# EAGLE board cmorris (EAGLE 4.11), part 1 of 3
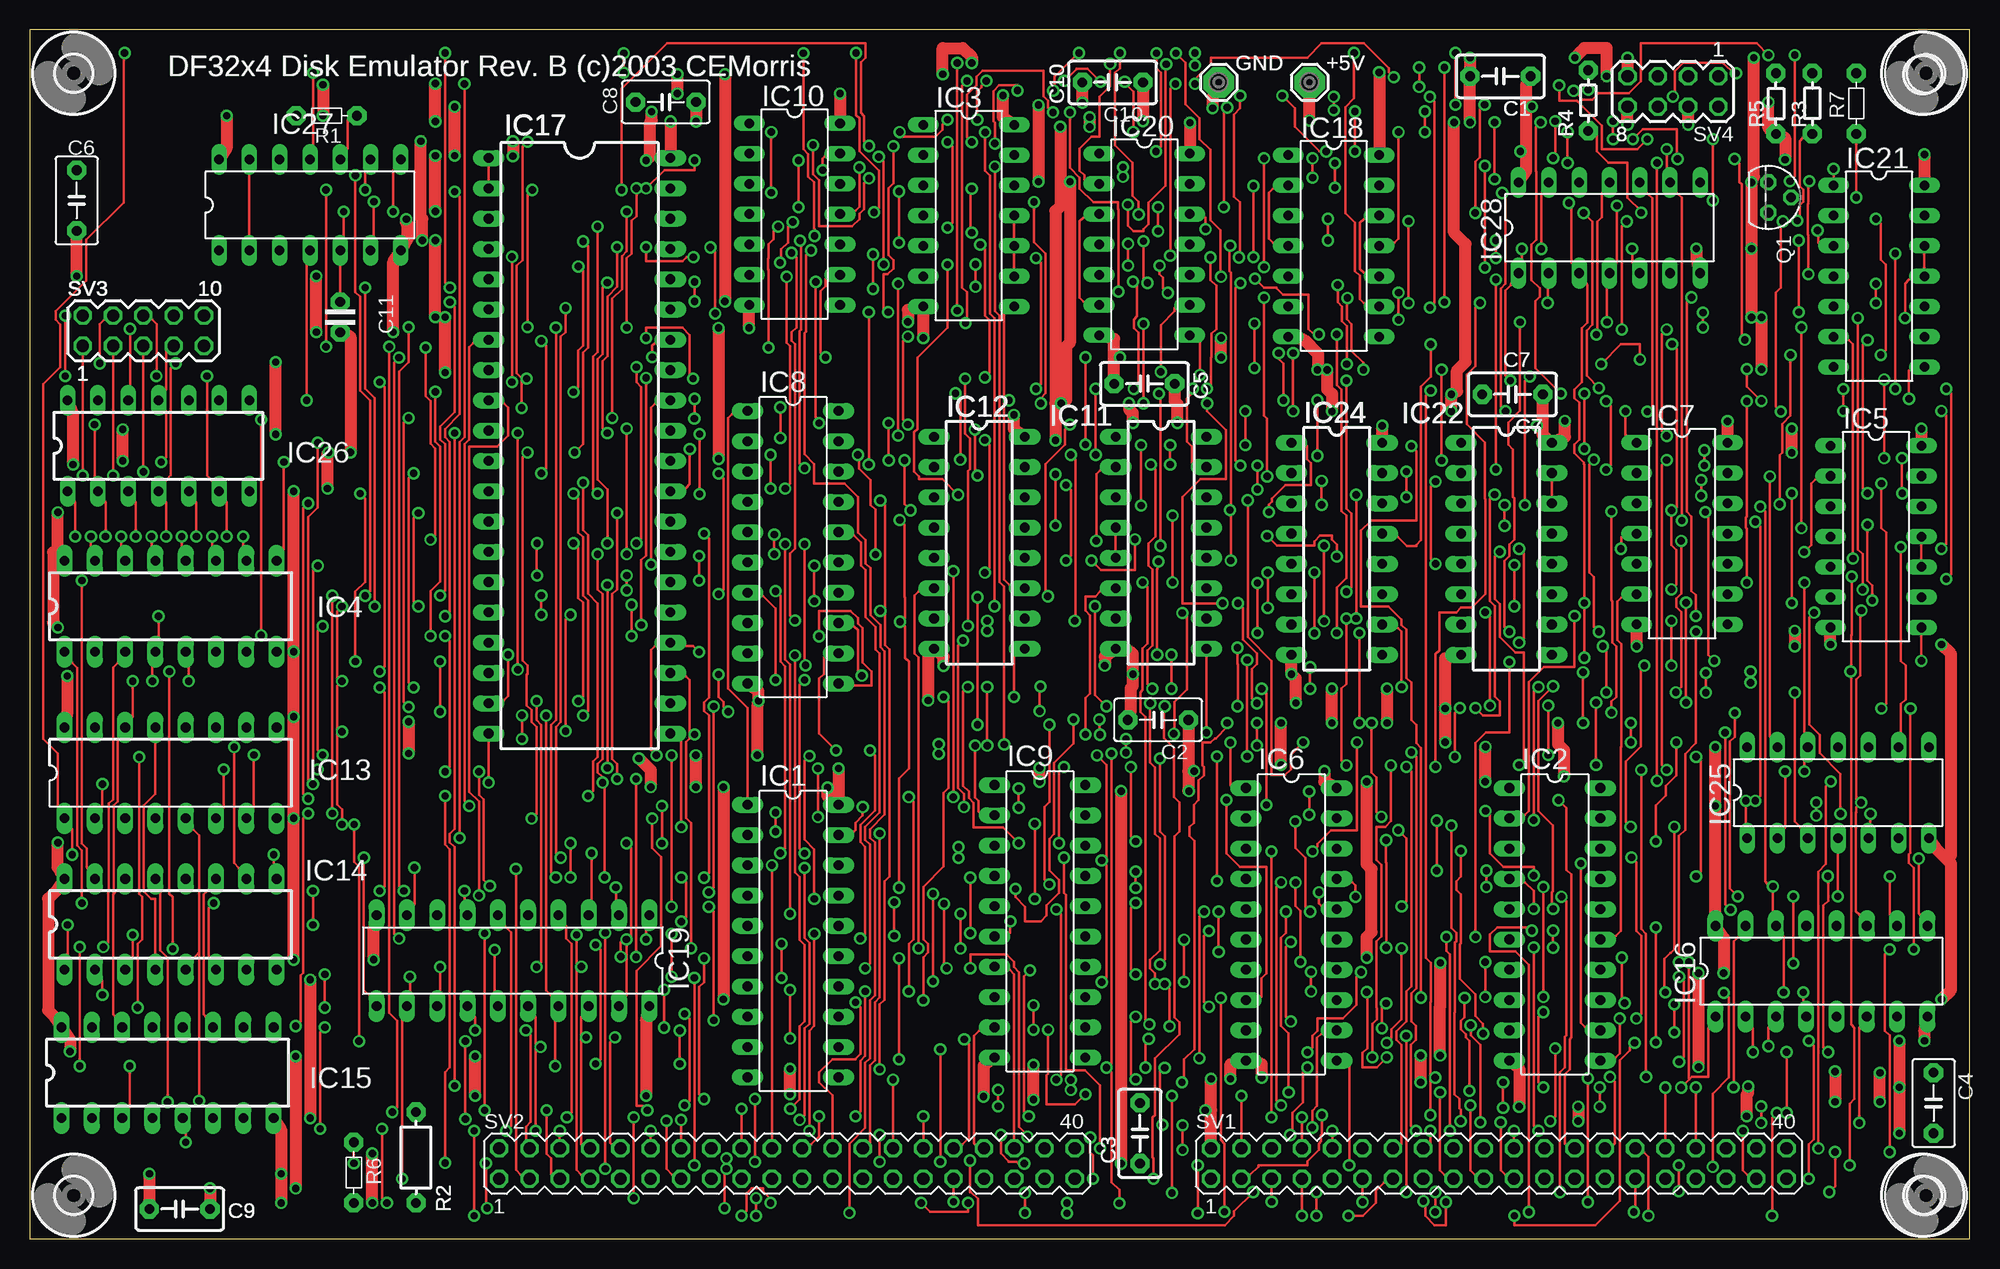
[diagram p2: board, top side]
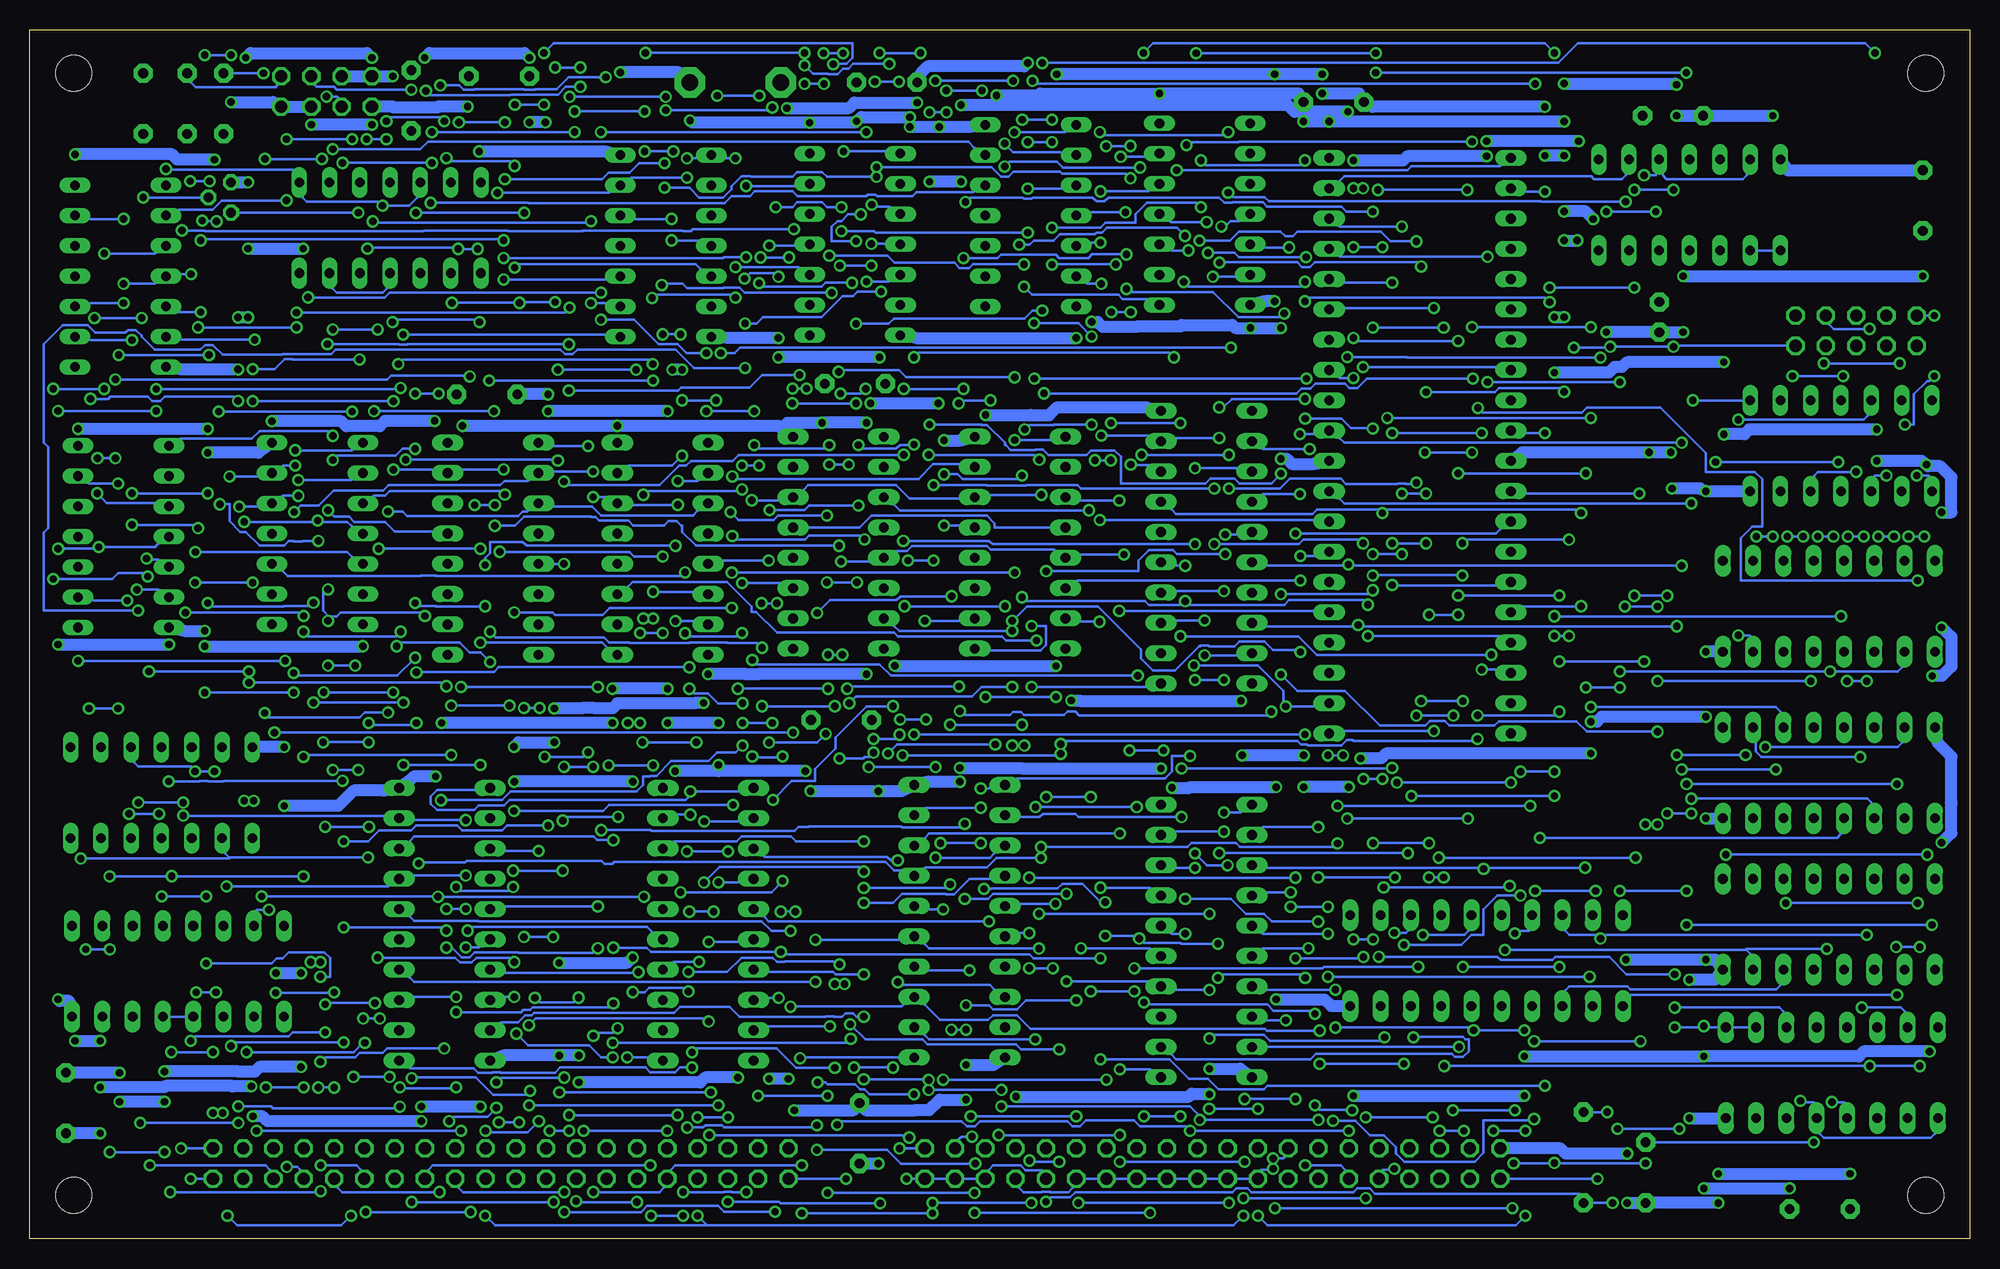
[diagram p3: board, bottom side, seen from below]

Size 162.67 x 101.4 mm. Coordinates in mm from the lower left corner, seen from the top.
Outline: 0,0 162.67,0 162.67,101.4 0,101.4 0,0
Copper layers (1*16): Top 0.035mm / dielectric 1.5mm / Bottom 0.035mm
Design rules "default": minimum track width 8mil, minimum drill 24mil, track to track 8mil, track to pad 8mil, pad to pad 8mil, via to via 8mil, smd to smd 8mil, copper to edge 40mil, drill to drill 8mil, minimum pad ring 10mil, minimum via ring 8mil, stop-mask expansion 4mil, vias tented up to drill 0mil, thermal gap 10mil
Net classes: 1 supply: width 1.016 mm

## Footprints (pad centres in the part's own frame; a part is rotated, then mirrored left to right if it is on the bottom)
SE14 = drill 1.397 pad 2.54 octagon: MP 0,0
C5B3.5 = drill 0.813 pad 1.6 octagon: 1 -2.54,0; 2 2.54,0
C-2,5 = drill 0.813 pad 1.6 octagon: 1 -1.27,0; 2 1.27,0
DIL20 = drill 0.813 long: 1 -11.43,-3.81; 2 -8.89,-3.81; 3 -6.35,-3.81; 4 -3.81,-3.81; 5 -1.27,-3.81; 6 1.27,-3.81; 7 3.81,-3.81; 8 6.35,-3.81; 9 8.89,-3.81; 10 11.43,-3.81; 11 11.43,3.81; 12 8.89,3.81; 13 6.35,3.81; 14 3.81,3.81; 15 1.27,3.81; 16 -1.27,3.81; 17 -3.81,3.81; 18 -6.35,3.81; 19 -8.89,3.81; 20 -11.43,3.81
DIL14 = drill 0.8 long: 1 -7.62,-3.81; 2 -5.08,-3.81; 3 -2.54,-3.81; 4 0,-3.81; 5 2.54,-3.81; 6 5.08,-3.81; 7 7.62,-3.81; 8 7.62,3.81; 9 5.08,3.81; 10 2.54,3.81; 11 0,3.81; 12 -2.54,3.81; 13 -5.08,3.81; 14 -7.62,3.81
DIL16 = drill 0.813 long: 1 -8.89,-3.81; 2 -6.35,-3.81; 3 -3.81,-3.81; 4 -1.27,-3.81; 5 1.27,-3.81; 6 3.81,-3.81; 7 6.35,-3.81; 8 8.89,-3.81; 9 8.89,3.81; 10 6.35,3.81; 11 3.81,3.81; 12 1.27,3.81; 13 -1.27,3.81; 14 -3.81,3.81; 15 -6.35,3.81; 16 -8.89,3.81
DIL40 = drill 0.813 long: 1 -24.13,-7.62; 2 -21.59,-7.62; 3 -19.05,-7.62; 4 -16.51,-7.62; 5 -13.97,-7.62; 6 -11.43,-7.62; 7 -8.89,-7.62; 8 -6.35,-7.62; 9 -3.81,-7.62; 10 -1.27,-7.62; 11 1.27,-7.62; 12 3.81,-7.62; 13 6.35,-7.62; 14 8.89,-7.62; 15 11.43,-7.62; 16 13.97,-7.62; 17 16.51,-7.62; 18 19.05,-7.62; 19 21.59,-7.62; 20 24.13,-7.62; 21 24.13,7.62; 22 21.59,7.62; 23 19.05,7.62; 24 16.51,7.62; 25 13.97,7.62; 26 11.43,7.62; 27 8.89,7.62; 28 6.35,7.62; 29 3.81,7.62; 30 1.27,7.62; 31 -1.27,7.62; 32 -3.81,7.62; 33 -6.35,7.62; 34 -8.89,7.62; 35 -11.43,7.62; 36 -13.97,7.62; 37 -16.51,7.62; 38 -19.05,7.62; 39 -21.59,7.62; 40 -24.13,7.62
TO92 = drill 0.813 octagon: 1 1.27,0; 2 0,1.905; 3 -1.27,0
R-5 = drill 0.813 pad 1.6 octagon: 1 -2.54,0; 2 2.54,0
R-7,5 = drill 0.813 pad 1.6 octagon: 1 -3.81,0; 2 3.81,0
MA20-2 = drill 1.016 octagon: 1 -24.13,-1.27; 2 -24.13,1.27; 3 -21.59,-1.27; 4 -21.59,1.27; 5 -19.05,-1.27; 6 -19.05,1.27; 7 -16.51,-1.27; 8 -16.51,1.27; 9 -13.97,-1.27; 10 -13.97,1.27; 11 -11.43,-1.27; 12 -11.43,1.27; 13 -8.89,-1.27; 14 -8.89,1.27; 15 -6.35,-1.27; 16 -6.35,1.27; 17 -3.81,-1.27; 18 -3.81,1.27; 19 -1.27,-1.27; 20 -1.27,1.27; 21 1.27,-1.27; 22 1.27,1.27; 23 3.81,-1.27; 24 3.81,1.27; 25 6.35,-1.27; 26 6.35,1.27; 27 8.89,-1.27; 28 8.89,1.27; 29 11.43,-1.27; 30 11.43,1.27; 31 13.97,-1.27; 32 13.97,1.27; 33 16.51,-1.27; 34 16.51,1.27; 35 19.05,-1.27; 36 19.05,1.27; 37 21.59,-1.27; 38 21.59,1.27; 39 24.13,-1.27; 40 24.13,1.27
MA05-2 = drill 1.016 octagon: 1 -5.08,-1.27; 2 -5.08,1.27; 3 -2.54,-1.27; 4 -2.54,1.27; 5 0,-1.27; 6 0,1.27; 7 2.54,-1.27; 8 2.54,1.27; 9 5.08,-1.27; 10 5.08,1.27
MA04-2 = drill 1.016 octagon: 1 -3.81,-1.27; 2 -3.81,1.27; 3 -1.27,-1.27; 4 -1.27,1.27; 5 1.27,-1.27; 6 1.27,1.27; 7 3.81,-1.27; 8 3.81,1.27
3,0 = hole 3: 0,0

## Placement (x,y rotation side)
+5V  SE14  [SE14]  107.31,96.99 0 top
C1  [C5B3.5]  123.31,97.5 180 top
C2  [C5B3.5]  94.61,43.52 180 top
C3  [C5B3.5]  93.09,8.85 90 top
C4  [C5B3.5]  159.63,11.39 270 top
C5  [C5B3.5]  93.47,71.72 180 top
C6  [C5B3.5]  3.93,87.08 270 top
C7  [C5B3.5]  124.33,70.83 180 top
C8  [C5B3.5]  53.34,95.34 180 top
C9  [C5B3.5]  12.57,2.5 180 top
C10  [C5B3.5]  90.8,96.99 180 top
C11  [C-2,5]  26.03,77.31 270 top
GND  SE14  [SE14]  99.69,96.99 0 top
IC1  74LS240N  [DIL20]  64,24.98 270 top
IC2  74LS244N  [DIL20]  127.88,26.38 270 top
IC3  74LS00N  [DIL14]  78.73,85.81 270 top
IC4  74LS138N  [DIL16]  11.81,53.05 0 top
IC5  74LS32N  [DIL14]  154.81,58.89 270 top
IC6  74LS244N  [DIL20]  105.79,26.38 270 top
IC7  74LS74N  [DIL14]  138.55,59.14 270 top
IC8  74LS240N  [DIL20]  64,58 270 top
IC9  74LS240N  [DIL20]  84.7,26.63 270 top
IC10  74LS04N  [DIL14]  64.13,85.94 270 top
IC11  74LS191N  [DIL16]  94.86,58.38 270 top
IC12  74LS191N  [DIL16]  79.62,58.38 270 top
IC13  74LS191N  [DIL16]  11.81,39.08 0 top
IC14  74LS191N  [DIL16]  11.81,26.38 0 top
IC15  74LS191N  [DIL16]  11.55,13.93 0 top
IC16  74LS191N  [DIL16]  150.24,22.44 0 top
IC17  DS1258  [DIL40]  46.1,66.51 270 top
IC18  74LS74N  [DIL14]  109.34,83.27 270 top
IC19  74LS240N  [DIL20]  40.51,23.33 180 top
IC20  74LS02N  [DIL14]  93.47,83.4 270 top
IC21  74LS01N  [DIL14]  155.06,80.73 270 top
IC22  74LS155N  [DIL16]  123.82,57.87 270 top
IC24  74LS155N  [DIL16]  109.6,57.87 270 top
IC25  74LS74N  [DIL14]  151.63,37.43 0 top
IC26  74LS30N  [DIL14]  10.79,66.51 0 top
IC27  74LS86N  [DIL14]  23.49,86.7 0 top
IC28  74LS07N  [DIL14]  132.46,84.8 0 top
Q1  2N3904  [TO92]  145.79,87.34 270 top
R1  1K  [R-5]  24.89,94.2 180 top
R2  1K  [R-7,5]  32.38,6.82 90 top
R3  220  [R-5]  149.47,95.21 270 top
R4  220  [R-5]  130.68,95.47 270 top
R5  220  [R-5]  146.43,95.21 90 top
R6  0  [R-5]  27.17,5.55 270 top
R7  4.7K  [R-5]  153.16,95.21 90 top
SV1  BUS1  [MA20-2]  123.19,6.31 0 top
SV2  BUS2  [MA20-2]  63.49,6.31 0 top
SV3  WRLOCK  [MA05-2]  9.52,76.16 0 top
SV4  PANEL LEDS  [MA04-2]  137.79,96.23 180 top
U$1  [3,0]  3.68,97.75 0 top
U$2  [3,0]  3.68,3.65 0 top
U$3  [3,0]  159,3.65 0 top
U$4  [3,0]  159,97.75 0 top

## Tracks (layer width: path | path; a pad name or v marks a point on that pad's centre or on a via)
0V  (via drill 0.61)
  Top 0.203: v58.41,6.74 v58.41,5.88 58.26,5.37 v58.26,2.58 | 14.13,23.93 14.19,23.99 14.19,33.85 13.71,34.33 IC13.5 | 14.13,23.93 13.71,23.51 IC14.5 | v13.08,8.09 13.08,8.8 IC15.5 | v14.19,11.57 14.19,23.86 14.13,23.93 | v38.35,2.58 38.25,2.68 v38.25,6.34 | R6.1 v27.17,6.34 | IC11.5 IC11.4 | v140.15,63.64 v140.15,62.32 | v147.06,20.66 147.06,25.31 IC16.14 146.17,27.57 v146.17,29.55 145.69,29.78 145.51,29.96 145.51,61 v145.11,61.41 | v148.71,20.66 148.71,19.95 IC16.4 | v94.64,56.81 94.56,56.73 94.56,56.17 94.53,56.15 v94.53,48.98 | v95.73,46.14 v95.73,48.98 | v103.3,46.14 103.7,45.73 v103.7,36.39 | v122.07,35.88 122.45,35.5 122.45,32.32 123.57,31.2 126.11,31.2 v126.11,30.47 | v34.82,6.36 34.82,13.98 35.22,14.39 35.22,32.68 34.82,33.08 v34.82,37.15 | v46.81,37.15 47.21,37.55 47.21,40.02 47.62,40.42 47.62,53.3 46.81,54.12 46.81,59.02 46.4,59.42 v46.4,63.41 | v62.12,65.75 v62.12,62.93 | v69.44,65.75 69.54,65.65 69.54,64.58 70.48,63.64 70.48,63.28 70.51,63.26 70.51,61.56 70.91,61.15 v70.91,57.39
  Bottom 0.203: SV2.33 79.7,4.28 79.34,3.92 77.82,3.92 77.8,3.95 77.14,3.95 77.11,3.92 75.59,3.92 75.23,4.28 SV2.29 SV2.27 SV2.25 SV2.23 SV2.21 SV2.19 SV2.17 59.38,5.8 58.49,5.8 v58.41,5.88 | v58.41,6.74 57.53,6.74 57.45,6.82 SV2.16 | IC15.1 2.92,8.8 3.25,8.47 12.24,8.47 12.57,8.8 IC15.5 13.08,11.44 14.07,11.44 v14.19,11.57 | v13.08,8.09 R6.1 | v38.35,2.58 v58.26,2.58 | v27.17,6.34 34.82,6.34 | 34.82,6.34 v38.25,6.34 | v140.15,62.32 141.42,62.32 IC7.12 143.66,61.41 v145.11,61.41 | v140.15,63.64 135.73,63.64 IC7.2 | IC16.5 IC16.4 | v148.71,20.66 v147.06,20.66 | v146.17,29.55 132.63,29.55 IC2.17 130.4,30.47 v126.11,30.47 | v94.64,56.81 92.32,56.81 IC11.5 90.06,57.7 89.1,57.7 88.69,58.1 82.39,58.1 82.11,57.82 76.78,57.82 76.73,57.77 IC12.5 74.52,57.39 v70.91,57.39 | v95.73,48.98 v94.53,48.98 | v95.73,46.14 95.75,46.17 103.27,46.17 v103.3,46.14 | v103.7,36.39 114.09,36.39 114.6,35.88 v122.07,35.88 | v46.81,37.15 v34.82,37.15 | v46.4,63.41 46.5,63.31 47.26,63.31 47.29,63.34 47.95,63.34 47.98,63.31 52.29,63.31 52.72,63.74 57.02,63.74 57.83,62.93 v62.12,62.93 | v69.44,65.75 v62.12,65.75 | v34.82,6.36 34.82,6.34
660-663\  (via drill 0.61)
  Top 0.203: v115.44,62.22 v115.44,64.35 | v141.24,48.48 140.74,48.98 140.74,60.72 v140.51,60.95 | v158.62,48.48 IC5.8 | v108.33,61.56 v108.33,63.56
  Bottom 0.203: v115.44,64.35 118.72,64.35 IC22.2 120.92,63.56 122.86,63.56 123.21,63.21 132.58,63.21 133.04,62.75 137.18,62.75 138.45,61.48 139.97,61.48 v140.51,60.95 | v115.44,62.22 114.45,62.22 IC24.14 112.11,61.56 v108.33,61.56 | v141.24,48.48 v158.62,48.48 | v108.33,63.56 106.7,63.56 IC24.2
(NED+EWL)\  (via drill 0.61)
  Top 0.203: v94.43,91.2 94.84,91.61 94.84,97.8 94.48,98.16 v94.48,99.43 | v96.11,99.43 96.9,98.64 96.9,95.16 98.09,93.97 98.09,92.24 99,91.33 99,85.43 99.84,84.59 99.84,80.73 v99.89,80.68 | v102.74,80.53 103.5,79.77 104.52,79.77 104.52,79.74 105.08,79.19 107.23,79.19 107.23,76.31 107.69,75.86 v108.1,75.86 | v109.6,75.86 109.6,71.62 110,71.21 110,61.05 110.41,60.64 110.41,55.44 109.6,54.62 v109.6,50.81 | v111.5,43.27 v111.5,50.81 | v112.52,43.27 112.52,39.1 112.92,38.7 112.92,35.8 v113.33,35.4 | v117.98,30.87 v117.98,35.07 | v122.14,29.5 v122.14,30.87 | v126.92,20.28 v126.92,29.5
  Bottom 0.203: v94.43,91.2 90.95,91.2 IC20.1 | v96.11,99.43 v94.48,99.43 | v99.89,80.68 100.2,80.99 102.28,80.99 v102.74,80.53 | v109.6,75.86 v108.1,75.86 | v111.5,50.81 v109.6,50.81 | v112.52,43.27 v111.5,43.27 | v113.33,35.4 117.65,35.4 v117.98,35.07 | v122.14,30.87 v117.98,30.87 | v122.14,29.5 122.47,29.17 126.59,29.17 v126.92,29.5 | v126.92,20.28 130.4,20.28 IC2.13
ACBUS\0  (via drill 0.61)
  Top 0.203: v67.61,40.96 66.19,42.38 66.19,46.98 66.59,47.38 66.59,48.76 IC8.12 | v70.45,40.96 70.86,40.55 70.86,35.93 69.64,34.71 69.64,33.29 70.05,32.88 70.05,25.59 v69.64,25.18 | v63.04,21.88 v63.04,24.75 | v55.72,6.16 v55.72,21.88 | v120.01,32.53 120.01,30.39 119.6,29.98 119.6,29.27 120.01,28.87 120.01,24.78 119.91,24.68 119.91,21.81 121.23,20.48 121.23,18.68 121.86,18.05 v121.86,17.21 | v113.79,15.23 112.95,14.39 111.76,14.39 111.76,15.58 112.16,15.99 112.16,20.64 v112.11,20.69 | v107.44,22.39 v107.44,20.74 | v94.76,23.02 95.17,23.43 95.17,33.74 94.76,34.15 v94.76,40.3 | v91.92,41.92 v91.92,40.78 | v89.73,42.28 89.68,42.33 v89.68,43.55 | v87.52,43.55 87.52,41.54 85.9,39.92 85.9,33.95 85.49,33.54 85.49,30.9 86.3,30.09 86.3,29.02 85.26,27.98 85.26,27.11 84.78,26.63 83.46,26.63 83.46,27.85 82.65,28.66 v82.65,29.35 | v72.49,25.41 v72.49,28.23
  Bottom 0.203: v70.45,40.96 v67.61,40.96 | v63.04,24.75 66.11,24.75 66.16,24.8 69.26,24.8 v69.64,25.18 70.12,25.41 v72.49,25.41 | v63.04,21.88 62.73,22.19 56.03,22.19 v55.72,21.88 | v55.72,6.16 52.72,6.16 52.37,5.8 SV2.11 | v120.01,32.53 122.78,32.53 IC2.3 | v121.86,17.21 120.87,16.22 115.77,16.22 114.78,15.23 v113.79,15.23 | v112.11,20.69 111.09,20.69 110.74,21.04 107.74,21.04 v107.44,20.74 | v107.44,22.39 104.19,22.39 102.99,23.58 100.38,23.58 100.02,23.23 99.36,23.23 99.33,23.25 94.99,23.25 v94.76,23.02 | v94.76,40.3 92.76,40.3 92.65,40.4 92.27,40.4 91.92,40.75 v91.92,40.78 | v91.92,41.92 90.09,41.92 v89.73,42.28 | v87.52,43.55 v89.68,43.55 | v82.65,29.35 82.06,29.35 82.04,29.38 76.5,29.38 76.09,29.78 74.39,29.78 72.84,28.23 v72.49,28.23
ACBUS\1  (via drill 0.61)
  Top 0.203: v48.25,5.88 v48.25,25.67 | v62.53,54.32 62.94,53.91 62.94,48.4 63.34,47.99 63.34,32.75 v62.94,32.35 | v47.11,32.35 47.11,28.46 IC19.3
  Bottom 0.203: v48.25,25.67 47.26,25.67 47.11,25.82 IC19.3 | v48.25,5.88 48.33,5.8 49.22,5.8 SV2.9 | v62.53,54.32 66.52,54.32 IC8.14 | v47.11,32.35 v62.94,32.35
ACBUS\2  (via drill 0.61)
  Top 0.203: 45.84,22.82 45.84,5.78 46.25,5.37 SV2.7 | 45.84,22.82 v45.84,25.49 | v70.05,22.7 70.45,23.1 70.45,33.06 70.05,33.47 70.05,34.53 71.27,35.75 71.27,49.09 70.91,49.44 70.91,51.32 70.1,52.13 70.1,56.07 69.69,56.48 69.69,58.41 69.11,58.99 IC8.16 | 45.84,22.82 v46.25,22.82
  Bottom 0.203: v45.84,25.49 42.36,25.49 42.03,25.82 IC19.5 | v70.05,22.7 54.27,22.7 54.15,22.82 v46.25,22.82
ACBUS\3  (via drill 0.61)
  Top 0.203: v36.44,29.17 36.44,28.46 IC19.7 | v31.36,29.17 30.96,29.58 30.96,72.73 31.77,73.55 v31.77,76.47 | v41.73,76.47 41.73,87.57 v42.13,87.97 | v49.63,87.97 49.63,96.46 53.44,100.27 70.1,100.27 70.1,99.07 69.69,98.67 69.69,94.42 69.97,94.15 69.97,92.06 v70.38,91.66 | v72.41,91.63 72.41,88.53 72,88.12 72,82.49 72.41,82.08 72.41,81.37 71.93,80.89 71.57,80.89 71.57,77.86 71.73,77.71 v71.98,77.71 | v70.35,64.94 v70.35,77.71 | v43.33,10.78 43.33,7.15 43.71,6.77 43.71,6.54 43.73,6.51 43.73,5.4 SV2.5 | v38.15,25.62 v38.15,10.78
  Bottom 0.203: v31.36,29.17 v36.44,29.17 | v41.73,76.47 v31.77,76.47 | v49.63,87.97 v42.13,87.97 | v70.38,91.66 70.4,91.63 v72.41,91.63 | v70.35,77.71 v71.98,77.71 | v70.35,64.94 70.33,64.91 68.83,64.91 IC8.18 | v38.15,10.78 v43.33,10.78 | v38.15,25.62 37.94,25.82 36.95,25.82 IC19.7
ACBUS\4  (via drill 0.61)
  Top 0.203: v32.25,31.13 32.25,28.08 IC19.9 | v40.76,31.03 40.76,5.78 41.17,5.37 SV2.3
  Bottom 0.203: 40.76,31.13 58.9,31.13 IC1.3 | 40.76,31.13 v32.25,31.13 | v40.76,31.03 40.76,31.13
ACBUS\5  (via drill 0.61)
  Top 0.203: v31.21,5.04 31.21,18.35 IC19.12 31.87,20.84 v31.87,21.98 | v53.82,21.98 v53.82,25.59
  Bottom 0.203: SV2.1 v31.21,5.04 | v53.82,25.59 59.28,25.59 IC1.5 | v31.87,21.98 v53.82,21.98
ACBUS\6  (via drill 0.61)
  Top 0.203: v37.33,17.49 37.33,18.58 IC19.14 | v41.6,17.49 42.01,17.08 42.01,9.82 41.6,9.41 41.6,8.34 SV2.4 | v53.18,17.72 v53.18,20.89
  Bottom 0.203: v37.33,17.49 v41.6,17.49 42.08,17.72 v53.18,17.72 | v53.18,20.89 58.9,20.89 IC1.7
ACBUS\7  (via drill 0.61)
  Top 0.203: v42.41,9.05 42.41,16.09 | 42.41,16.09 42.41,18.58 IC19.16 | v44.45,9.05 SV2.6 | 42.41,16.09 v42.82,16.09
  Bottom 0.203: v44.45,9.05 v42.41,9.05 | v42.82,16.09 IC1.9
ACBUS\8  (via drill 0.61)
  Top 0.203: 46.25,16.9 46.25,18.55 IC19.18 | 46.25,16.9 46.25,7.91 SV2.8 | 46.25,16.9 v46.65,16.9
  Bottom 0.203: v46.65,16.9 46.63,16.93 42.49,16.93 42.29,16.73 42.01,16.73 42.01,15.73 42.49,15.25 43.15,15.25 43.4,15.51 54.83,15.51 55.27,15.07 66.54,15.07 66.9,15.43 IC1.12
ACBUS\9  (via drill 0.61)
  Top 0.203: v49.07,16.9 48.66,16.5 48.66,8.04 48.79,7.91 SV2.10 | v63.75,20.87 v63.75,16.8 | v115.03,27.88 115.44,28.28 115.44,33.59 v114.75,34.28 | v84.27,28.51 v84.27,34.81 | v75.74,21.6 v75.74,28.94
  Bottom 0.203: v49.07,16.9 49.35,16.62 58.69,16.62 59.18,17.11 63.44,17.11 v63.75,16.8 | v63.75,20.87 66.54,20.87 IC1.14 68.96,21.6 v75.74,21.6 | v115.03,27.88 122.78,27.88 IC2.5 | v114.75,34.28 110.61,34.28 110.54,34.2 98.55,34.2 98.19,34.56 97.35,34.56 97.33,34.58 89.61,34.58 89.53,34.51 84.58,34.51 v84.27,34.81 | v84.27,28.51 82.32,28.51 81.89,28.94 v75.74,28.94
ACBUS\10  (via drill 0.61)
  Top 0.203: v65.78,25.59 65.78,17.87 65.38,17.46 v65.38,9.05 | v52.06,9.05 SV2.12 | v111.63,22.36 111.22,21.96 111.22,19.62 110.1,18.5 107.97,18.5 107.97,17.46 107.54,17.03 107.54,16.04 v107.13,15.63 | v95.17,14.34 94.76,14.34 94.76,9.77 v94.97,9.56
  Bottom 0.203: v65.78,25.59 66.9,25.59 IC1.16 | v52.06,9.05 v65.38,9.05 65.7,9.44 69.57,9.44 70.07,9.94 74.09,9.94 74.59,9.44 75.26,9.44 75.66,9.84 83,9.84 83.41,9.44 84.09,9.44 84.53,9.87 94.66,9.87 v94.97,9.56 | v111.63,22.36 111.68,22.31 122.78,22.31 IC2.7 | v107.13,15.63 106.8,15.96 100.05,15.96 98.42,14.34 v95.17,14.34
ACBUS\11  (via drill 0.61)
  Top 0.203: v64.56,9.97 64.97,10.38 64.97,17.64 65.38,18.05 65.38,24.83 64.97,25.23 v64.97,31.1 | v54.6,9.97 SV2.14 | v92.73,18.63 92.32,18.23 92.32,13.78 v92.73,13.37 | v87.3,12.48 v87.3,13.32 | v81.2,11.11 v81.2,12.48
  Bottom 0.203: v54.6,9.97 v64.56,9.97 64.77,10.48 65.4,11.11 v81.2,11.11 | v64.97,31.1 66.52,31.1 IC1.18 | v92.73,18.63 93.34,18.63 93.62,18.91 94.28,18.91 94.56,18.63 95.22,18.63 95.25,18.66 95.91,18.66 95.96,18.61 103.14,18.61 103.98,19.44 108.15,19.44 108.66,18.94 120.39,18.94 120.57,18.76 121.15,18.76 121.74,18.17 123.13,18.17 123.16,18.15 IC2.9 | v92.73,13.37 87.35,13.37 v87.3,13.32 | v81.2,12.48 v87.3,12.48
ACCLEAR\  (via drill 0.61)
  Top 0.203: v133.09,86.65 133.09,81.93 IC28.4 132.25,79.69 v132.25,76.87 | v151.25,89.73 IC21.1 | v94.23,5.04 94.23,6.74 94.15,6.82 94.15,10.17 94.36,10.38 94.36,15.13 96.39,17.16 96.39,18.17 95.98,18.58 95.98,33.74 96.39,34.15 96.39,36.61 95.93,37.07 95.93,41.19 95.12,42 95.12,44.62 v95.17,44.67 | v101.27,44.67 101.29,44.69 101.29,48.17 101.27,48.2 v101.27,49.57 | v124.07,50.91 123.67,51.32 123.67,56.86 124.07,57.26 124.07,58.23 124.48,58.64 124.48,62.12 124.38,62.22 124.38,66.2 123.97,66.61 123.97,68.47 124.96,69.46 v124.96,76.87
  Bottom 0.203: IC28.4 132.74,79.69 133.07,79.36 136.93,79.36 137.26,79.69 IC28.6 | IC28.12 130.19,87.31 130.86,86.65 v133.09,86.65 133.47,86.98 139.47,86.98 139.8,87.31 IC28.8 140.58,89.67 151.2,89.67 v151.25,89.73 | v101.27,44.67 v95.17,44.67 | v101.27,49.57 101.67,49.98 104.16,49.98 104.19,50 107.34,50 107.36,49.98 112.39,49.98 112.42,50 114.09,50 114.52,50.43 123.59,50.43 v124.07,50.91 | v124.96,76.87 125.17,77.08 132.05,77.08 v132.25,76.87 | v94.23,5.04 SV1.1
BAC1  (via drill 0.61)
  Top 0.203: v9.04,19.39 9.04,24.73 9.44,25.13 9.44,28.66 9.16,28.94 v9.16,40.4
  Bottom 0.203: v9.04,19.39 5.79,19.39 5.46,19.06 IC15.15 | v9.16,40.4 17.47,40.4 17.95,40.88 17.95,41.57 IC13.10
BAC2  (via drill 0.61)
  Top 0.203: v3.55,32.22 3.55,34.33 IC13.1 2.36,36.28 2.36,40.7 1.14,41.92 1.14,71.69 2.56,73.11 2.56,76.67 2.15,77.08 2.15,77.79 4.75,80.38 4.75,83.78 7.87,86.91 7.87,99.38 v7.95,99.45 | v20.44,32.22 20.44,31.51 IC14.9 | v119.98,9.87 120.01,9.89 120.01,10.81 119.88,10.94 119.88,11.72 119.48,12.13 119.48,18.96 119.5,18.99 119.5,24.85 119.6,24.96 119.6,25.67 119.2,26.07 v119.2,34.66 | v136.34,33.34 136.34,36.36 137.18,37.2 137.18,37.99 138.07,38.88 v138.07,41.64 | v134.26,43.27 v134.26,41.64 | v130.25,47.51 v130.25,43.27 | v107.36,46.14 v107.36,47.94 | v102.89,44.92 102.48,45.33 102.48,47.79 102.89,48.2 102.89,49.11 101.72,50.28 101.72,52.9 v101.32,53.3 | v100.02,53.3 96.64,53.3 96.64,62.19 98.17,63.72 100.3,63.72 100.3,67.83 98.73,69.41 v98.73,70.07 | v93.39,76.75 v93.39,70.07 | v77.77,98.62 v77.77,77.84 | v124.45,9.05 SV1.22
  Bottom 0.203: v20.44,32.22 v3.55,32.22 | v124.45,9.05 124.33,8.93 120.92,8.93 v119.98,9.87 | v119.2,34.66 122.65,34.66 123.06,34.25 126.41,34.25 126.82,34.66 130.27,34.66 130.68,34.25 133.37,34.25 134.28,33.34 v136.34,33.34 | v138.07,41.64 138.04,41.67 134.28,41.67 v134.26,41.64 | v134.26,43.27 134.08,43.09 130.42,43.09 v130.25,43.27 | v130.25,47.51 130.22,47.54 123.74,47.54 123.34,47.94 v107.36,47.94 | v107.36,46.14 106.98,45.76 105.81,45.76 104.97,44.92 v102.89,44.92 | v100.02,53.3 v101.32,53.3 | v93.39,70.07 v98.73,70.07 | v93.39,76.75 90.65,76.75 90.22,77.18 79.24,77.18 78.58,77.84 v77.77,77.84 | v77.77,98.62 34.49,98.62 32.84,100.27 8.76,100.27 v7.95,99.45
BAC3  (via drill 0.61)
  Top 0.203: v17.14,41.24 17.14,31.51 17.52,31.13 IC14.10
  Bottom 0.203: v17.14,41.24 6.04,41.24 5.71,41.57 IC13.15
BAC4  (via drill 0.61)
  Top 0.203: v78.66,51.4 78.66,64.38 78.84,64.55 78.84,67.12 78.43,67.53 v78.43,72.15 | v55.62,72.15 55.34,72.43 55.34,73.52 55.32,73.55 55.32,74.97 55.34,74.99 55.34,75.81 54.73,76.42 51.68,76.42 v51.68,75.55 | v42.9,75.3 43.3,74.89 43.3,64.61 v42.9,64.2 | v32.18,64.2 31.77,63.79 31.77,46.65 v32.18,46.24 | v29.33,46.24 29.74,45.83 29.74,29.58 v29.33,29.17 | v23.74,26.33 v23.74,29.17 | v3.17,26.33 3.17,23.89 IC14.1 | v128.19,36.79 128.85,36.13 128.85,30.95 129.26,30.54 129.26,16.88 129.13,16.75 129.13,14.21 128.72,13.8 128.72,7.99 128.8,7.91 SV1.26 | v102.89,43.27 v102.89,41.36 | v100.4,43.27 100.4,42.91 99.46,41.97 99.36,41.97 99,41.62 98.32,41.62 98.32,39.71 98.45,39.59 98.45,38.88 98.01,38.44 98.01,36.79 97.61,36.39 97.61,34.89 97.25,34.53 97.25,33.8 97.66,33.39 97.66,15.91 96.79,15.05 96.79,13.27 96.64,13.12 v96.62,13.12 | v88.51,12.13 87.65,11.27 85.26,11.27 85.26,13.7 85.39,13.83 v85.39,17.54 | v84.17,19.6 v84.17,17.54 | v74.93,20 74.93,23.61 75.33,24.02 75.33,24.73 74.93,25.13 74.93,29.53 76.63,31.23 76.63,37.4 77.03,37.81 77.03,45.05 v76.63,45.45 | v82.52,45.45 82.52,48.83 IC12.9
  Bottom 0.203: v78.66,51.4 77.44,51.4 77.44,49.82 77.92,49.34 82.14,49.34 IC12.9 | v55.62,72.15 v78.43,72.15 | v51.68,75.55 51.43,75.3 v42.9,75.3 | v32.18,64.2 v42.9,64.2 | v29.33,46.24 v32.18,46.24 | v23.74,29.17 v29.33,29.17 | v3.17,26.33 v23.74,26.33 | v128.19,36.79 123.06,36.79 122.35,37.5 111.78,37.5 111.22,38.06 111.22,38.77 110.66,38.77 110.61,38.82 110.13,38.82 108.89,40.07 105.76,40.07 105.05,40.78 103.48,40.78 v102.89,41.36 | v100.4,43.27 v102.89,43.27 | v96.62,13.12 95.93,13.12 95.75,12.94 93.47,12.94 93.06,12.54 92.65,12.54 92.25,12.13 v88.51,12.13 | v84.17,17.54 v85.39,17.54 | v84.17,19.6 82.24,19.6 81.91,19.27 79.88,19.27 79.14,20 v74.93,20 | v82.52,45.45 v76.63,45.45
BAC5  (via drill 0.61)
  Top 0.203: v132.51,13.58 132.91,13.17 132.91,8.01 132.81,7.91 SV1.28 | v135.53,13.58 135.53,25.59 135.12,26 v135.12,39.33 | v137.26,39.33 136.85,39.74 136.85,64.91 v137.26,65.32 | v130.35,70.88 v130.35,66.26 | v128.39,70.88 126.26,73.01 126.26,78.65 126.61,79.01 126.61,79.72 125.93,80.4 125.93,83.38 126.34,83.78 126.34,89.5 126.28,89.55 126.28,93.23 v126.69,93.64 | v122.83,88.86 v122.83,93.64 | v109.44,88.15 v109.44,90.21 | v91.66,89.88 v91.66,89.06 | v70.38,88.94 69.97,88.53 69.97,86.37 69.57,85.97 69.57,85.53 68.96,84.92 66.16,84.92 66.16,88.79 65.68,89.27 v65.68,91.73 | v41.73,92.01 41.32,91.61 41.32,82.08 40.84,81.6 40.84,72.61 41.24,72.2 | v41.24,69.69 41.24,72.2 | v4.36,55.21 4.36,33.16 4.77,32.75 4.77,31.18 4.82,31.13 IC14.15 | v87.62,51.83 87.7,51.91 87.7,65.34 v87.3,65.75 | v78.02,65.34 78.02,70.5 v77.62,70.9 | v41.65,72.15 41.32,72.15 41.24,72.2
  Bottom 0.203: v135.53,13.58 v132.51,13.58 | v137.26,39.33 v135.12,39.33 | v137.26,65.32 136.88,65.7 131.97,65.7 131.41,66.26 v130.35,66.26 | v128.39,70.88 v130.35,70.88 | v122.83,93.64 v126.69,93.64 | v122.83,88.86 114.68,88.86 114.14,89.4 112.39,89.4 111.58,90.21 v109.44,90.21 | v109.44,88.15 107.36,88.15 106.55,87.34 104.52,87.34 103.83,88.02 103.83,88.28 103.04,89.06 103.02,89.06 102.94,89.14 102.28,89.14 102.2,89.06 98.73,89.06 98.32,89.47 96.24,89.47 95.83,89.06 v91.66,89.06 | v91.66,89.88 82.04,89.88 81.25,89.09 80.59,89.09 80.18,89.5 76.27,89.5 76.12,89.34 70.79,89.34 v70.38,88.94 | v65.68,91.73 65.43,91.99 61.31,91.99 61.28,92.01 v41.73,92.01 | v41.24,69.69 40.86,69.3 32.51,69.3 32.1,69.71 25.93,69.71 22.12,65.9 22.12,64.3 18.84,64.3 18.82,64.33 18,64.33 17.39,63.72 17.39,59.73 18.23,59.73 19.17,58.79 19.17,55.21 v4.36,55.21 | v87.62,51.83 84.73,51.83 IC12.10 | v87.3,65.75 87.27,65.72 78.41,65.72 v78.02,65.34 | v77.62,70.9 56.46,70.9 56.05,71.31 55.29,71.31 54.86,71.74 52.39,71.74 52.01,71.36 51.35,71.36 50.57,72.15 v41.65,72.15
BAC6  (via drill 0.61)
  Top 0.203: v155.98,30.39 155.98,27.22 IC16.10 | v139.72,30.39 140.13,30.8 140.13,40.02 v139.72,40.42 | v127.33,44.72 v127.33,40.58 | v122.45,44.72 122.45,52.13 v122.04,52.54 | v103.81,55.87 v103.81,52.92 | v80.08,55.87 80.49,56.27 80.49,66.59 v80.08,66.99 | v135.73,1.94 135.73,6.87 135.35,7.25 SV1.30 | v146.1,1.94 146.1,10.15 v146.5,10.55 | v147.31,15.66 v147.31,10.55 | v150.8,15.66 150.39,16.07 150.39,27.95 150.8,28.36 150.8,30.39 v150.77,30.42
  Bottom 0.203: v139.72,30.39 150.77,30.39 | 150.77,30.39 v155.98,30.39 | v139.72,40.42 139.57,40.58 v127.33,40.58 | v122.45,44.72 v127.33,44.72 | v122.04,52.54 118.82,52.54 118.61,52.34 114.62,52.34 114.04,52.92 v103.81,52.92 | v80.08,55.87 v103.81,55.87 | v80.08,66.99 77.11,66.99 IC12.1 | v135.73,1.94 136.55,1.13 145.28,1.13 v146.1,1.94 | v147.31,10.55 v146.5,10.55 | v150.8,15.66 v147.31,15.66 | v150.77,30.42 150.77,30.39
BAC7  (via drill 0.61)
  Top 0.203: 139.17,13.39 139.37,13.58 140.74,13.58 140.74,17.67 IC16.1 | 139.17,13.39 v138.48,12.69 | v137.16,12.69 SV1.32 | v103.75,63.95 103.75,68.8 103.5,69.05 v103.5,78.93 | v110.48,78.91 110.43,78.85 110.43,77.13 110.84,76.72 110.84,74.46 111.83,73.47 v111.83,72.89 | v118.38,65.27 v118.38,72.89 | v131.16,65.34 130.75,64.94 130.75,55.89 131.16,55.49 131.16,51.32 v131.57,50.91 | v139.72,50.91 139.72,41.59 138.81,40.68 138.81,34.3 138.3,33.8 v138.3,23.2 | v139.11,23.2 139.11,13.45 139.17,13.39
  Bottom 0.203: v138.48,12.69 v137.16,12.69 | v103.75,63.95 103.53,63.72 88.16,63.72 86.91,64.96 84.73,64.96 IC12.15 | v103.5,78.93 103.75,79.19 110.21,79.19 v110.48,78.91 | v118.38,72.89 v111.83,72.89 | v118.38,65.27 118.46,65.34 v131.16,65.34 | v131.57,50.91 131.95,50.53 133.73,50.53 133.75,50.51 134.39,50.51 134.41,50.53 139.34,50.53 v139.72,50.91 | v139.11,23.2 v138.3,23.2
BAC8  (via drill 0.61)
  Top 0.203: v142.16,42.46 142.16,28.05 v142.62,27.6 | v98.67,42.46 IC11.9 | v142.87,12.71 142.87,24.93 143.25,25.31 IC16.15 | v139.69,12.71 SV1.34
  Bottom 0.203: v142.16,42.46 v98.67,42.46 | v142.62,27.6 142.64,27.57 143.63,27.57 IC16.15 | v142.87,12.71 v139.69,12.71
BAC11  (via drill 0.61)
  Top 0.203: v97.53,71.31 97.45,71.23 97.45,70.88 97.05,70.47 97.05,66.87 97.45,66.46 97.45,65.09 IC11.15 | v98.7,71.31 99.06,71.67 99.06,73.9 99.08,73.93 99.08,75.91 99.49,76.31 99.49,79.92 99,80.4 v99,82.31 | v101.39,82.31 101.47,82.39 101.47,86.93 100.98,87.41 100.98,94.3 101.49,94.81 v101.49,95.87 | v105.02,95.87 106.09,94.81 106.09,93.26 108.15,91.2 v108.71,91.2 | v111.12,94.55 v111.12,91.2 | v116.99,92.82 v116.99,94.55 | v128.95,90.23 v128.95,92.82 | v136.44,38.42 v136.44,90.23 | v151.02,38.37 150.62,37.96 150.62,31.43 149.96,30.77 149.96,27.98 149.98,27.95 v149.98,7.58
  Bottom 0.203: v98.7,71.31 v97.53,71.31 | v101.39,82.31 v99,82.31 | v105.02,95.87 v101.49,95.87 | v111.12,91.2 v108.71,91.2 | v116.99,94.55 v111.12,94.55 | v128.95,92.82 v116.99,92.82 | v136.44,90.23 v128.95,90.23 | v136.44,38.42 146.35,38.42 146.4,38.37 147.7,38.37 147.75,38.42 148.43,38.42 148.48,38.37 v151.02,38.37 | SV1.40 v149.98,7.58
BADDAC\  (via drill 0.61)
  Top 0.203: v116.23,9.05 115.82,9.46 115.82,16.27 116.23,16.68 116.23,17.84 115.84,18.23 115.84,20.59 116.25,20.99 116.25,40.4 v115.84,40.81 | v119.5,40.42 119.5,44.11 v119.91,44.51 | v121.23,44.51 121.86,43.88 123.26,43.88 123.26,45.07 122.86,45.48 122.86,53.07 122.45,53.48 122.45,62.04 v122.83,62.42 | v109.22,9.05 SV1.10
  Bottom 0.203: v116.23,9.05 v109.22,9.05 | v115.84,40.81 116.23,40.42 v119.5,40.42 | v121.23,44.51 v119.91,44.51 | v122.83,62.42 123.13,62.73 132.48,62.73 132.89,62.32 133.8,62.32 IC7.3
BBREAK\  (via drill 0.61)
  Top 0.203: v104.11,32.5 v104.11,10.2 | v107.56,32.5 107.97,32.91 107.97,33.13 109.09,34.25 111.3,34.25 v111.3,41.64 | v106.78,41.64 105.73,40.6 105.73,39.38 105.25,38.9 104.11,38.9 104.11,48.48 102.13,50.46 v102.13,61.94 | v106.68,10.2 SV1.8 | v66.49,89.62 66.49,90.59 66.65,90.74 IC10.13 | IC17.1 IC17.2 | v8.63,46.77 8.63,43.83 IC13.14 7.39,41.92 7.39,36.69 7.03,36.34 7.03,29.04 7.09,28.98 | v10.28,46.77 10.28,47.92 IC4.4 10.79,50.56 v10.79,52.21 | 7.09,28.98 6.98,28.87 6.98,18.81 7.11,18.68 IC15.14 | 7.09,28.98 7.36,29.25 IC14.14 | v35.63,87.82 36.04,87.41 36.04,69.15 34.82,67.93 34.82,67.22 35.22,66.81 35.22,52.62 v34.82,52.21 | v77.85,62.4 76.53,63.72 74.57,63.72 74.57,63.95 74.16,64.35 74.16,67.65 74.44,67.93 74.44,73.9 76.96,76.42 v76.96,81.7 | v71.6,81.73 71.6,90.34 v71.19,90.74
  Bottom 0.203: v104.11,10.2 v106.68,10.2 | v107.56,32.5 v104.11,32.5 | v106.78,41.64 v111.3,41.64 | v102.13,61.94 99.97,61.94 IC11.14 97.76,62.85 97.4,63.21 90.04,63.21 88.9,62.07 84.73,62.07 IC12.14 82.14,62.4 v77.85,62.4 | v66.49,89.62 47.16,89.62 46.81,89.98 39.39,89.98 IC17.1 | v10.28,46.77 v8.63,46.77 | v35.63,87.82 37.18,87.82 IC17.2 | v10.79,52.21 v34.82,52.21 | v76.96,81.7 76.93,81.73 v71.6,81.73 | v71.19,90.74 69.23,90.74 IC10.13
BIOP1  (via drill 0.61)
  Top 0.203: v116.86,3.16 117.01,3.01 117.01,1.92 117.8,1.13 118.74,1.13 v118.74,3.09 | v130.65,13.47 v130.65,3.09 | v120.72,12.41 120.72,16.6 120.42,16.9 120.42,17.16 120.01,17.56 120.01,18.27 120.31,18.58 v120.31,20.21 | v116.66,20.23 116.66,41.16 116.25,41.57 116.25,43.12 115.84,43.52 115.84,46.65 115.44,47.05 115.44,51.09 115.03,51.5 115.03,51.93 113.91,53.05 111.63,53.05 111.63,59.4 112.49,60.26 116.25,60.26 116.25,66.08 v115.84,66.48 | v111.76,3.09 SV1.11
  Bottom 0.203: v111.76,3.09 116.78,3.09 v116.86,3.16 | v130.65,3.09 v118.74,3.09 | v130.65,13.47 130.58,13.55 125.29,13.55 123.82,12.08 121.05,12.08 v120.72,12.41 | v120.31,20.21 119.93,19.82 117.06,19.82 v116.66,20.23 | v115.84,66.48 118.72,66.48 IC22.1
BIOP2  (via drill 0.61)
  Top 0.203: v110.56,1.94 111.78,1.94 112.87,3.04 112.87,4.03 113.56,4.71 SV1.13 | v107.89,3.92 v107.89,1.94 | v102.59,3.92 100.98,2.32 100.98,1.92 100.2,1.13 79.5,1.13 79.5,3.37 78.94,3.92 78.84,3.92 v78.84,6.57 | v76.35,15.89 v76.35,6.46 | v93.87,18 93.54,18.33 93.54,43.78 93.14,44.18 93.14,45.83 93.31,46.01 93.31,49.52 93.72,49.92 93.72,54.65 v93.31,55.06 | v95.83,60.67 v95.83,55.06 | v103.91,60.95 103.91,61.58 104.16,61.84 104.16,62.09 105.28,63.21 107.41,63.21 107.41,65.06 107.08,65.39 107.08,66.48 IC24.1
  Bottom 0.203: v107.89,1.94 v110.56,1.94 | v107.89,3.92 104.49,3.92 104.47,3.95 103.81,3.95 103.78,3.92 v102.59,3.92 | v78.84,6.57 78.73,6.46 v76.35,6.46 | v76.35,15.89 79.55,15.89 79.95,16.29 87.4,16.29 87.83,16.73 92.6,16.73 v93.87,18 | v95.83,55.06 v93.31,55.06 | v95.83,60.67 99.92,60.67 100.3,60.29 103.25,60.29 v103.91,60.95
BMB0  (via drill 0.61)
  Top 0.203: v118.26,12.28 118.26,5.75 118.64,5.37 SV1.17 | v105.56,12.28 105.56,17.23 104.92,17.87 104.92,25.26 105.33,25.67 v105.33,27.45 | v107.36,27.45 106.95,27.85 106.95,31.94 106.12,32.78 v106.12,35.01
  Bottom 0.203: v105.56,12.28 v118.26,12.28 | v107.36,27.45 v105.33,27.45 | v106.12,35.01 103.27,35.01 IC6.2
BMB1  (via drill 0.61)
  Top 0.203: v104.92,29.91 104.52,29.5 104.52,11.59 v104.92,11.19 | v120.8,11.19 120.8,5.75 121.18,5.37 SV1.19
  Bottom 0.203: v104.92,29.91 103.27,29.91 IC6.4 | v120.8,11.19 v104.92,11.19
BMB2  (via drill 0.61)
  Top 0.203: v123.34,9.77 123.34,5.75 123.72,5.37 SV1.21 | v121.64,9.77 121.64,16.27 120.82,17.08 v120.82,17.92 | v105.73,18.23 105.33,18.63 105.33,24.5 v105.73,24.91
  Bottom 0.203: v121.64,9.77 v123.34,9.77 | v120.82,17.92 120.24,18.5 106.02,18.5 v105.73,18.23 | v105.73,24.91 103.27,24.91 IC6.6
BMB3  (via drill 0.61)
  Top 0.203: v80.11,92.8 80.11,89.57 80.51,89.17 80.51,77.61 80.89,77.23 v80.89,53.05 | v89.33,53.05 89.33,45.63 v90.29,44.67 | v100.35,36.82 100.35,32.32 101.47,31.2 103.7,31.2 103.7,22.26 103.27,21.83 103.27,20.31 IC6.8 | v117.85,2.25 v117.85,3.92 | v100.17,2.27 100.17,7.99 99.87,8.29 v99.87,20.21
  Bottom 0.203: v80.11,92.8 80.08,92.82 75.89,92.82 IC3.1 | v89.33,53.05 v80.89,53.05 | v90.29,44.67 92.5,44.67 95.12,42.05 95.12,41.11 96.82,39.41 96.82,38.39 98.78,38.39 v100.35,36.82 | v117.85,3.92 126.34,3.92 126.69,4.28 SV1.23 | v117.85,2.25 111.43,2.25 110.89,2.78 104.97,2.78 104.47,2.27 v100.17,2.27 | v99.87,20.21 100.68,20.21 IC6.8
BMB4  (via drill 0.61)
  Top 0.203: v110.64,6.16 110.64,14.41 IC6.11 | v80.92,91.86 80.92,93.59 80.79,93.71 80.79,96.25 81.28,96.74 82.82,96.74 v82.82,96.3 | v85.82,96.3 85.92,96.41 85.92,97.47 87.9,99.45 v87.98,99.45 | v91.41,99.45 91.41,98.18 91,97.78 91,91.71 92.48,90.23 92.48,87.49 92.98,86.98 v92.98,85.92 | v93.39,83.68 93.39,80.51 v93.72,80.17 | v101.52,80.15 101.11,79.74 101.11,65.27 v101.52,64.86 | v102.94,62.85 v102.94,64.86 | v111.22,52.03 v111.22,62.4 | v110.41,52.03 110.41,46.55 110,46.14 110,40.12 v110.41,39.71 | v114.14,39.71 114.14,35.04 113.66,34.56 112.92,34.56 112.92,31.76 113.33,31.36 113.33,25.36 112.92,24.96 112.92,19.39 112.97,19.34 112.97,18.43 112.57,18.02 v112.57,15.23
  Bottom 0.203: v110.64,6.16 128.88,6.16 129.23,5.8 SV1.25 | v80.92,91.86 80.21,91.15 76.22,91.15 IC3.2 | v85.82,96.3 v82.82,96.3 | v91.41,99.45 v87.98,99.45 | v92.98,85.92 94.05,85.92 94.61,85.36 94.94,85.36 95.42,84.87 95.42,83.68 v93.39,83.68 | v93.72,80.17 95.93,80.17 96.26,79.84 101.21,79.84 v101.52,80.15 | v102.94,64.86 v101.52,64.86 | v102.94,62.85 103.09,62.7 110.92,62.7 v111.22,62.4 | v110.41,52.03 v111.22,52.03 | v114.14,39.71 v110.41,39.71 | v112.57,15.23 110.89,15.23 IC6.11
BMB6  (via drill 0.61)
  Top 0.203: v134.51,2.25 134.62,2.35 SV1.29 | v125.7,2.25 125.7,22.97 124.58,24.09 122.45,24.09 122.45,25.51 123.06,26.12 125.95,26.12 v125.95,25.84 | v155.27,63.34 155.27,59.63 155.67,59.22 155.67,44.9 v155.27,44.49 | v157.7,44.49 157.7,32.37 157.58,32.25 157.58,31.53 157.98,31.13 v157.98,24.27 | v155.95,24.27 155.55,23.86 155.55,17.46 155.95,17.06 v155.95,7.28 | v151.38,7.28 151.38,4.41 v150.9,3.92 | v138.27,6.16 v138.27,4
  Bottom 0.203: v125.7,2.25 v134.51,2.25 | v125.95,25.84 125.65,26.15 110.89,26.15 110.51,25.77 IC6.15 | v155.27,63.34 157.68,63.34 IC5.13 | v157.7,44.49 v155.27,44.49 | v155.95,24.27 v157.98,24.27 | v151.38,7.28 v155.95,7.28 | v150.9,3.92 138.35,3.92 v138.27,4 | v138.27,6.16 135.28,6.16 134.92,5.8 SV1.29
BMB7  (via drill 0.61)
  Top 0.203: v111.17,28.69 111.17,29.63 110.89,29.91 IC6.17 | v128.44,28.69 128.85,28.28 128.85,17.06 128.72,16.93 128.72,14.39 128.32,13.98 v128.32,3.92 | v132.63,61 132.61,60.97 132.61,53.56 132.71,53.45 132.71,50.03 133.04,49.7 133.04,45.45 132.63,45.05 v132.63,44.13 | v142.97,44.11 142.97,42.1 142.56,41.69 142.56,29.38 v143.23,28.71
  Bottom 0.203: IC24.3 106.7,61.02 107.06,60.67 114.78,60.67 115.51,61.41 118.72,61.41 IC22.3 120.92,61.02 120.95,61 121.36,61 121.74,60.62 131.03,60.62 131.41,61 v132.63,61 | v111.17,28.69 v128.44,28.69 128.93,28.71 v143.23,28.71 | v128.32,3.92 136.5,3.92 136.85,4.28 SV1.31 | v132.63,44.13 134.59,44.13 135,43.73 142.59,43.73 v142.97,44.11
BMB8  (via drill 0.61)
  Top 0.203: v129.53,52.24 129.53,47.97 126.97,47.97 125.7,46.7 125.7,35.88 125.37,35.55 IC2.2 | v137.66,54.47 138.07,54.88 138.07,57.77 137.66,58.18 v137.66,61.1 138.12,61.35 138.12,74.64 v137.71,75.04 | v117.47,75.02 117.47,72.3 116.66,71.49 116.66,58.59 116.25,58.18 116.25,58.1 115.46,58.1 114.7,58.87 IC24.13 | v141.12,6.03 141.12,12.18 142.46,13.53 142.46,20.23 v142.06,20.64 | v137.16,20.66 137.08,20.74 137.08,23.48 137.56,23.96 137.59,23.96 137.89,24.27 v137.89,34.56 | v134.23,34.56 133.83,34.96 133.83,40.04 135.07,41.29 135.07,47.77 v135.38,48.07 | v137.66,51.83 v137.66,48.07
  Bottom 0.203: v129.53,52.24 129.81,52.52 136.62,52.52 136.93,52.21 137.59,52.21 | 137.59,52.21 138.07,52.69 138.07,54.47 v137.66,54.47 | v137.66,61.1 137.13,60.57 135.88,60.57 135.45,60.14 132.89,60.14 132.08,59.32 128.93,59.32 IC22.13 | v117.47,75.02 117.5,75.04 130.98,75.04 131.03,74.99 131.69,74.99 131.75,75.04 v137.71,75.04 | v141.12,6.03 140.23,6.03 140,5.8 SV1.33 | v142.06,20.64 137.18,20.64 v137.16,20.66 | v134.23,34.56 v137.89,34.56 | v137.66,48.07 v135.38,48.07 | v137.66,51.83 137.61,51.88 137.61,52.11 137.59,52.21
BMB9  (via drill 0.61)
  Top 0.203: v156.43,71.28 v156.43,82.64 | v160.7,71.28 161.11,70.88 161.11,55.74 v160.7,55.33 | v152.78,55.54 152.78,50.66 152.75,50.64 152.75,47.59 | 152.75,47.59 152.75,35.95 152.72,35.93 152.72,17.97 153,17.69 153,11.72 152.6,11.32 v152.6,6.16 | v98.6,84.67 98.6,85.64 98.57,85.66 IC20.12 | v149.91,84.57 149.96,84.52 149.96,83.55 IC21.3 | v126.11,27.67 126.11,29.17 125.37,29.91 IC2.4 | v127.73,27.67 127.63,27.77 127.63,29.04 127.73,29.15 127.73,34.66 126.51,35.88 126.51,45.12 v127.73,46.34 | v144.29,47.59 v144.29,46.65 | v152.67,47.59 152.75,47.59
  Bottom 0.203: v156.43,82.64 152.19,82.64 IC21.3 | v160.7,71.28 v156.43,71.28 | v160.7,55.33 155.75,55.33 155.24,55.84 153.08,55.84 v152.78,55.54 | v152.6,6.16 142.9,6.16 142.54,5.8 SV1.35 | v98.6,84.67 107.08,84.67 107.23,84.52 107.89,84.52 107.92,84.54 116.3,84.54 116.33,84.52 122.55,84.52 122.6,84.57 129.59,84.57 129.64,84.52 147.95,84.52 148,84.57 v149.91,84.57 | v127.73,27.67 v126.11,27.67 | v127.73,46.34 128.04,46.65 v144.29,46.65 | v152.67,47.59 v144.29,47.59
BMB10  (via drill 0.61)
  Top 0.203: v126.11,24.45 126.11,9.46 v126.51,9.05 | v143.66,9.05 143.66,5.75 144.04,5.37 SV1.37
  Bottom 0.203: v126.11,24.45 124.99,24.45 IC2.6 | v143.66,9.05 v126.51,9.05
BMB11  (via drill 0.61)
  Top 0.203: v122.04,23.2 v122.04,20.28 | v133.5,23.58 133.5,20 v133.73,19.77 | v137.89,17.31 v137.89,19.67 | v149.17,16.6 149.58,16.19 149.58,8.34 149.17,7.94 v149.17,5.04
  Bottom 0.203: v122.04,20.28 122.78,20.28 IC2.8 | v122.04,23.2 122.42,23.58 125.22,23.58 125.62,23.18 126.59,23.18 127,23.58 v133.5,23.58 | v133.73,19.77 137.79,19.77 v137.89,19.67 | v137.89,17.31 140.63,17.31 140.97,16.98 148.79,16.98 v149.17,16.6 | SV1.39 v149.17,5.04
DATA0\  (via drill 0.61)
  Top 0.203: v64.16,48.93 64.16,30.75 64.56,30.34 64.56,25.06 64.97,24.65 64.97,18.23 64.56,17.82 64.56,11.7 v63.77,10.91 | SV2.18 v59.68,10.91
  Bottom 0.203: v64.16,48.93 61.49,48.93 IC8.9 | v59.68,10.91 v63.77,10.91
DATA1\  (via drill 0.61)
  Top 0.203: v62.53,46.88 62.53,52.87 61.49,53.91 IC8.7 | v64.97,46.88 64.56,46.47 64.56,32.73 v64.97,32.32 | SV2.20 v62.22,31.33
  Bottom 0.203: v64.97,46.88 v62.53,46.88 | v64.97,32.32 63.98,31.33 v62.22,31.33
DATA2\  (via drill 0.61)
  Top 0.203: v62.43,57.42 v62.43,59.07 | v77.44,37.05 v77.44,55.99 | v73.71,37.05 74.11,36.64 74.11,25.13 73.71,24.73 v73.71,20.77 | v70.05,20.77 70.05,15.33 69.64,14.92 69.64,10.68 v69.23,10.27 | v66.19,10.27 66.19,8.6 65.5,7.91 SV2.22
  Bottom 0.203: v62.43,59.07 61.49,59.07 IC8.5 | v62.43,57.42 66.47,57.42 66.8,57.75 68.83,57.75 69.69,56.88 69.69,55.99 v77.44,55.99 | v73.71,37.05 v77.44,37.05 | v70.05,20.77 v73.71,20.77 | v66.19,10.27 v69.23,10.27
DATA3\  (via drill 0.61)
  Top 0.203: v69.23,19.82 69.64,19.42 69.64,15.51 69.23,15.1 69.23,15.07 67.31,15.07 66.19,13.96 66.19,13.14 67.31,12.03 SV2.24 | v54.91,18.86 55.32,18.45 55.32,11.59 v54.91,11.19 | v51.79,10.78 51.4,11.16 50.87,11.16 50.87,22.49 52.95,24.57 52.95,32.04 52.19,32.8 v52.19,35.24 | v42.08,35.24 42.49,35.65 42.49,42.94 42.08,43.35 42.08,44.34 41.68,44.74 41.68,47.33 41.73,47.38 41.73,48.1 41.32,48.5 41.32,65.55 v41.73,65.95 | v45.69,65.95 46.4,66.66 46.4,74.33 46.81,74.74 46.81,83.25 v46.4,83.66 | v64.59,83.71 64.69,83.6 64.69,76.26 64.56,76.14 64.56,65.04 v64.97,64.63
  Bottom 0.203: v69.23,19.82 69.06,19.65 58.9,19.65 58.39,19.14 55.19,19.14 v54.91,18.86 | v54.91,11.19 54.53,10.81 51.81,10.81 v51.79,10.78 | v42.08,35.24 v52.19,35.24 | v45.69,65.95 v41.73,65.95 | v46.4,83.66 48.56,83.66 49.37,84.47 56.36,84.47 56.74,84.09 57.4,84.09 57.78,84.47 61.28,84.47 62.05,83.71 v64.59,83.71 | v64.97,64.63 61.49,64.63 IC8.3
DATA4\  (via drill 0.61)
  Top 0.203: v71.27,34 71.27,20.23 70.86,19.82 70.86,14.97 70.45,14.57 70.45,8.04 SV2.26
  Bottom 0.203: v71.27,34 87.24,34 87.6,33.64 IC9.18
DATA5\  (via drill 0.61)
  Top 0.203: v86.08,27.62 86.48,27.22 86.48,13.75 v86.08,13.35 | SV2.28 v72.39,13.35
  Bottom 0.203: v86.08,27.62 87.22,27.62 IC9.16 | v72.39,13.35 v86.08,13.35
DATA6\  (via drill 0.61)
  Top 0.203: v83.87,22.52 83.36,22.01 83.36,10.68 v83.76,10.27 | SV2.30 v74.93,10.27
  Bottom 0.203: v83.87,22.52 87.24,22.52 IC9.14 | v74.93,10.27 v83.76,10.27
DATA7\  (via drill 0.61)
  Top 0.203: v78.35,16.73 78.76,16.32 78.76,8.47 78.2,7.91 SV2.32
  Bottom 0.203: v78.35,16.73 87.24,16.73 87.6,17.08 IC9.12
DATA8\
  Top 0.203: IC9.9 79.6,17.46 79.17,17.03 79.17,8.01 79.27,7.91 SV2.34
DATA9\
  Top 0.203: IC9.7 82.19,22.54 82.55,22.19 SV2.36
DATA10\  (via drill 0.61)
  Top 0.203: v83.66,8.57 83.66,8.67 82.95,9.38 82.95,22.36 82.52,22.8 82.52,23.23 81.91,23.84 78.86,23.84 v78.86,22.7 | v76.88,22.7 76.65,22.92 v76.65,28.11
  Bottom 0.203: v83.66,8.57 84.55,8.57 84.78,8.34 SV2.38 | v76.88,22.7 v78.86,22.7 | v76.65,28.11 79.6,28.11 IC9.5
DATA11\  (via drill 0.61)
  Top 0.203: v89.73,7.58 89.73,12.89 88.49,14.13 86.89,14.13 86.89,28.84 86.71,29.02 v86.71,31.97
  Bottom 0.203: v86.71,31.97 82.16,31.97 81.81,32.32 IC9.3 | v89.73,7.58 SV2.40
DATA_IN  (via drill 0.61)
  Top 0.203: v53.39,9.89 53.39,5.85 53.87,5.37 SV2.13 | v36.52,16.57 v36.52,10.05 | v27.61,16.57 27.61,31.2 27.2,31.61 v27.2,34.76 | v26.18,34.76 26.18,36.03 25.78,36.44 25.78,42.53 | 25.78,42.53 25.78,46.37 v26.18,46.77 25.78,47.08 25.78,52.62 v26.18,53.02 | v13.33,46.77 13.33,47.92 IC4.5 | v154.35,35.65 154.35,34.91 IC25.5 | v151.84,35.65 151.84,39 150.08,40.75 150.08,42.28 149.22,43.14 149.22,52.11 v149.63,52.52 | v139.69,52.24 139.69,53.99 139.34,54.34 139.34,60.59 138.93,61 138.93,78.55 v139.34,78.96 | v114.78,77.08 v114.78,79.36 | v105.94,69.41 v105.94,74.28 | v101.93,66.56 v101.93,69.41 | v95.63,64.94 v95.63,66.56 | v94,64.94 94.41,64.53 94.41,58.89 93.82,58.31 93.82,56.45 94.13,56.15 94.13,49.75 93.72,49.34 93.72,46.55 v94.13,46.14 | v84.76,46.32 84.68,46.24 v84.68,44.26 | v58.57,44.21 58.16,44.62 58.16,45.02 57.75,45.43 v57.75,47.33 | 25.78,42.53 v26.18,42.53 | v70.79,86.09 71.19,86.5 71.19,89.57 69.57,91.2 69.57,93.97 69.29,94.25 v69.29,99.45 | v34.82,99.45 34.82,80.17 v35.22,79.77 | v28.11,79.77 28.11,71.31 28.93,70.5 v28.93,53.02
  Bottom 0.203: v53.39,9.89 51.51,9.89 50.31,8.7 49.12,8.7 48.1,7.68 48.1,7.12 48.05,7.12 47.39,6.46 41.5,6.46 40.76,7.2 40.76,9.94 36.62,9.94 v36.52,10.05 | v27.61,16.57 v36.52,16.57 | v26.18,34.76 v27.2,34.76 | v13.33,46.77 v26.18,46.77 | v151.84,35.65 v154.35,35.65 | v149.63,52.52 139.97,52.52 v139.69,52.24 | v139.34,78.96 137.1,78.96 137.08,78.93 132.91,78.93 132.48,79.36 v114.78,79.36 | v114.78,77.08 112.01,77.08 109.95,75.02 108.35,75.02 107.62,74.28 v105.94,74.28 | v101.93,69.41 v105.94,69.41 | v101.93,66.56 101.62,66.26 95.93,66.26 v95.63,66.56 | v94,64.94 v95.63,64.94 | v94.13,46.14 93.95,46.32 v84.76,46.32 | v84.68,44.26 84.35,43.93 80.46,43.93 80.21,44.18 79.55,44.18 79.29,43.93 75.97,43.93 75.66,44.23 75,44.23 74.67,43.9 58.87,43.9 v58.57,44.21 | v57.75,47.33 56.36,45.94 52.37,45.94 49.47,43.04 45.64,43.04 45.26,43.42 44.01,43.42 43.63,43.04 39.85,43.04 39.49,43.4 32.96,43.4 32.1,42.53 v26.18,42.53 | v70.79,86.09 73.63,86.09 IC3.4 | v69.29,99.45 68.47,100.27 35.63,100.27 v34.82,99.45 | v28.11,79.77 v35.22,79.77 | v26.18,53.02 v28.93,53.02
DISK_LED  (via drill 0.61)
  Top 0.203: v130.68,96.38 R4.1
  Bottom 0.203: v130.68,96.38 136.93,96.38 137.16,96.61 138.63,96.61 138.75,96.74 SV4.3
DMA0  (via drill 0.61)
  Top 0.203: v18.79,40.58 18.79,36.21 IC13.7 | v24.56,40.58 24.15,40.98 24.15,50.97 v24.56,51.37 | v51.68,72.2 51.68,57.32 51.28,56.91 v51.28,51.47
  Bottom 0.203: v24.56,40.58 v18.79,40.58 | 51.28,51.37 58.9,51.37 IC8.8 | 51.28,51.37 v24.56,51.37 | v51.68,72.2 52.8,72.2 IC17.33 | v51.28,51.47 51.28,51.37
DMA1  (via drill 0.61)
  Top 0.203: v16.25,39.36 16.25,36.21 IC13.6 | v24.15,39.36 23.74,39.76 23.74,56.05 v24.15,56.45 | v52.09,56.55 52.09,69.71 52.42,70.04 IC17.32
  Bottom 0.203: v24.15,39.36 v16.25,39.36 | 52.09,56.45 58.9,56.45 IC8.6 | 52.09,56.45 v24.15,56.45 | v52.09,56.55 52.09,56.45
DMA2  (via drill 0.61)
  Top 0.203: v6.09,38.14 6.09,36.21 IC13.2 | v23.74,38.14 23.34,38.55 23.34,60.52 24.15,61.33 v24.15,66.76 | v56.15,67.5 v56.15,62.47
  Bottom 0.203: v23.74,38.14 v6.09,38.14 | v24.15,66.76 52.45,66.76 52.8,67.12 IC17.31 55.01,67.5 v56.15,67.5 | v56.15,62.47 59.28,62.47 IC8.4
DMA3  (via drill 0.61)
  Top 0.203: v23.34,36.92 22.93,37.33 22.93,61.28 v23.34,61.68 | v55.34,66.23 55.34,63.31 55.01,62.98 IC17.29
  Bottom 0.203: v23.34,36.92 8.58,36.92 8.25,36.59 IC13.3 | v23.34,61.68 52.45,61.68 52.8,62.04 IC17.29 | v55.34,66.23 59.28,66.23 IC8.2
DMA4  (via drill 0.61)
  Top 0.203: v72.89,29.45 72.89,38.62 73.71,39.43 73.71,48.4 73.38,48.73 73.38,51.35 v72.97,51.75 73.38,52.06 73.38,53.79 73.35,53.81 73.35,59.88 v72.94,60.29
  Bottom 0.203: v72.89,29.45 68.73,29.45 IC1.17 | v72.97,51.75 74.52,51.75 IC12.7 | v72.94,60.29 55.01,60.29 IC17.28
DMA5  (via drill 0.61)
  Top 0.203: v74.52,24.37 74.52,48.76 74.19,49.09 74.19,53.96 74.52,54.29 IC12.6 | v56.13,55.21 v56.13,57.26
  Bottom 0.203: v74.52,24.37 68.73,24.37 IC1.15 | v56.13,57.26 54.93,57.26 IC17.27 | v56.13,55.21 74.87,55.21 IC12.6
DMA7  (via drill 0.61)
  Top 0.203: v71.27,14.21 71.27,19.65 71.67,20.05 71.67,29.98 72.08,30.39 72.08,49.44 71.73,49.8 71.73,52.67 | 71.73,52.67 71.73,61.51 v71.32,61.91 | 71.73,52.67 v71.32,52.67
  Bottom 0.203: v71.27,14.21 68.73,14.21 IC1.11 | v71.32,61.91 74.52,61.91 IC12.3 | v71.32,52.67 55.01,52.67 IC17.25
DMA8  (via drill 0.61)
  Top 0.203: v52.55,40.55 52.09,41.01 52.09,49.39 52.42,49.72 IC17.24 55.01,49.72 55.62,49.72 v56.13,49.21 | v53.82,27.85 v53.82,40.55 | v56.94,27.85 57.35,27.45 v57.35,18.33 | v80.28,51.83 v80.28,50.99
  Bottom 0.203: v53.82,40.55 v52.55,40.55 | v56.94,27.85 v53.82,27.85 | v57.35,18.33 58.92,18.33 IC1.8 | v80.28,50.99 89.76,50.99 90.14,51.37 IC11.7 | v80.28,51.83 79.06,53.05 73.1,53.05 69.49,49.44 69.49,48.68 68.47,47.66 66.65,47.66 64.61,49.7 64.56,49.7 64.49,49.77 63.82,49.77 63.75,49.7 61.64,49.7 61.23,50.1 59.15,50.1 58.44,49.39 56.31,49.39 v56.13,49.21
DMA9  (via drill 0.61)
  Top 0.203: v55.44,24.37 55.44,34.89 55.04,35.29 55.04,41.67 55.34,41.97 55.34,42.3 | 55.34,42.3 55.34,43.14 55.32,43.17 55.32,44.49 55.34,44.51 55.34,46.85 55.01,47.18 IC17.23 | v88.51,42.3 88.51,45.35 88.92,45.76 88.92,52.29 88.51,52.69 88.51,53.89 89.35,53.89 89.76,54.29 IC11.6 | 55.34,42.3 v55.75,42.3
  Bottom 0.203: v55.44,24.37 59.28,24.37 IC1.6 | v55.75,42.3 v88.51,42.3
DMA10  (via drill 0.61)
  Top 0.203: v57.35,44.64 57.35,29.48 v56.94,29.07 | v89.43,58.53 89.43,64.12 89.76,64.45 IC11.2 | v64.97,58.26 64.97,48.17 v65.04,48.1
  Bottom 0.203: v56.94,29.07 58.9,29.07 IC1.4 | IC17.22 55.01,44.64 v57.35,44.64 57.55,45.15 57.55,45.96 59.68,48.1 v65.04,48.1 | v89.43,58.53 82.24,58.53 81.96,58.26 v64.97,58.26
DMA11  (via drill 0.61)
  Top 0.203: v54.63,34.53 54.63,41.72 IC17.21 | v73.86,61.1 73.35,61.61 v73.35,65.29 | v72.03,65.29 72,65.32 v72,68.42 | v66.19,68.42 65.93,68.67 65.93,68.87 65.91,68.9 v65.91,80.25 | v55.75,78.63 v55.75,80.25 | v35.22,78.55 35.63,78.14 35.63,69.33 34.41,68.11 34.41,67.04 34.82,66.64 34.82,54.37 v34.41,53.96 | v42.9,52.34 v42.9,53.96 | v45.33,52.34 44.93,51.93 v44.93,42.58
  Bottom 0.203: v54.63,34.53 59.28,34.53 IC1.2 | v73.86,61.1 89.71,61.1 90.14,61.53 IC11.3 | v72.03,65.29 v73.35,65.29 | v66.19,68.42 v72,68.42 | v65.91,80.25 65.53,79.87 56.13,79.87 v55.75,80.25 | v55.75,78.63 55.42,78.96 48.94,78.96 48.91,78.93 35.61,78.93 v35.22,78.55 | v42.9,53.96 v34.41,53.96 | v45.33,52.34 v42.9,52.34 | v44.93,42.58 52.42,42.58 IC17.21
DQ0  (via drill 0.61)
  Top 0.203: v66.19,50.53 66.19,52.67 68.83,52.67 69.44,52.06 69.44,51.63 69.84,51.22 69.84,48.32 70.58,47.59 70.58,46.39 69.11,46.39 IC8.11 | v40.1,48.98 40.1,45.53 39.77,45.2 IC17.19 | v92.73,33.34 92.32,33.74 v92.32,39.56 | v86.71,39.56 86.3,39.15 v86.3,33.19 | v82.93,33.19 81.61,34.51 79.14,34.51 79.14,36.56 78.73,36.97 78.73,37.5 78.25,37.99 78.25,45.89 v78.66,46.29
  Bottom 0.203: v66.19,50.53 56.28,50.53 54.73,48.98 v40.1,48.98 | v92.73,33.34 98.42,33.34 98.83,33.74 102.99,33.74 103.4,33.34 108.63,33.34 IC6.18 | v86.71,39.56 v92.32,39.56 | v82.93,33.19 v86.3,33.19 | v78.66,46.29 69.11,46.29 IC8.11
DQ1  (via drill 0.61)
  Top 0.203: v64.16,51.85 63.75,52.26 63.75,57.49 64.16,57.9 64.16,75.04 63.88,75.32 63.88,76.03 64.28,76.44 64.28,82.28 v63.88,82.69 | v55.65,82.33 55.06,82.33 54.73,82 51.68,82 v51.68,83.17 | v49.25,83.17 49.25,79.84 48.43,79.03 48.43,74.03 48.03,73.62 48.03,67.98 v48.43,67.58 | v40.91,47.74 v40.91,67.58 | v108.1,29.07 108.1,28.13 108.3,27.93 IC6.16 | v99.54,40.45 v99.54,30.01 | v102.08,48.55 v102.08,40.45 | v69.77,47.23 69.44,47.56 69.44,51.04 69.11,51.37 IC8.13
  Bottom 0.203: v64.16,51.85 66.52,51.85 IC8.13 | v63.88,82.69 61.64,82.69 61.28,82.33 v55.65,82.33 | v49.25,83.17 v51.68,83.17 | v40.91,67.58 v48.43,67.58 | v40.91,47.74 39.77,47.74 IC17.18 | v108.1,29.07 100.48,29.07 v99.54,30.01 | v99.54,40.45 99.61,40.37 102,40.37 v102.08,40.45 | v102.08,48.55 101.7,48.17 91.41,48.17 90.47,47.23 v69.77,47.23
DQ2  (via drill 0.61)
  Top 0.203: v50.46,53.18 v50.46,50.56 | v65.78,56.45 v65.78,53.48 | v106.55,23.23 106.55,27.5 106.14,27.9 v106.14,29.88 | v92.73,29.43 v92.73,30.8 | v85.49,29.73 85.09,30.14 85.09,36.23 85.49,36.64 v85.49,43.12 | v79.47,53.81 v79.47,43.12
  Bottom 0.203: v50.46,50.56 39.49,50.56 IC17.17 | v50.46,53.18 50.85,53.56 57.09,53.56 57.47,53.18 65.48,53.18 v65.78,53.48 66.19,53.18 68.83,53.18 69.16,53.51 79.17,53.51 v79.47,53.81 | v65.78,56.45 66.52,56.45 IC8.15 | v106.55,23.23 108.68,23.23 IC6.14 | v106.14,29.88 104.85,31.18 93.11,31.18 v92.73,30.8 | v92.73,29.43 85.8,29.43 v85.49,29.73 | v79.47,43.12 v85.49,43.12
DQ3  (via drill 0.61)
  Top 0.203: v32.58,60.87 32.18,60.47 32.18,53.45 v32.58,53.05 | v107.54,9.33 107.54,10.73 107.95,11.14 107.95,16.85 108.3,17.21 IC6.12 | v96.67,7.46 v96.67,9.51 | v83.38,6.31 82.9,6.31 82.75,6.46 82.09,6.46 82.09,6.51 81.43,7.18 v81.43,8.7 | v71.27,6.46 v71.27,8.7 | v60.8,11.72 v60.8,6.46 | v56.53,11.72 56.13,12.13 56.13,21.12 56.53,21.53 v56.53,23.53 | v50.85,38.57 v50.85,23.63 | v49.25,38.57 49.25,39.84 48.84,40.25 48.84,54.06 49.25,54.47 v49.25,60.87
  Bottom 0.203: 49.25,61.18 32.89,61.18 v32.58,60.87 | 49.25,61.18 54.73,61.18 55.11,60.8 66.54,60.8 66.9,61.15 IC8.17 | v32.58,53.05 37.41,53.05 IC17.16 | v107.54,9.33 107.51,9.36 106.19,9.36 106.02,9.54 104.62,9.54 104.44,9.36 96.82,9.36 v96.67,9.51 | v96.67,7.46 90.78,7.46 89.63,6.31 v83.38,6.31 | v71.27,8.7 v81.43,8.7 | v60.8,6.46 v71.27,6.46 | v60.8,11.72 60.78,11.75 56.56,11.75 v56.53,11.72 | v56.53,23.53 50.95,23.53 v50.85,23.63 | v49.25,38.57 v50.85,38.57 | 49.25,61.18 v49.25,60.87
DQ4  (via drill 0.61)
  Top 0.203: v48.43,39.48 v48.43,54.83 | v66.09,35.37 v66.09,39.46 | v95.58,17.82 95.58,20.97 v95.17,21.37 | v94.36,21.37 94.36,22.26 93.95,22.67 93.95,23.38 94.76,24.19 94.76,33.57 94.36,33.97 94.36,39.54 93.95,39.94 v93.95,44.92 | v80.28,41.36 v80.28,46.29 | v79.27,41.36 79.27,37.02 79.55,36.74 79.55,35.85 79.6,35.8 IC9.2
  Bottom 0.203: v48.43,54.83 48.41,54.8 39.77,54.8 IC17.15 | v48.43,39.48 48.46,39.46 v66.09,39.46 | v66.09,35.37 74.72,35.37 75,35.65 77.72,35.65 78,35.37 79.6,35.37 IC9.2 | v95.58,17.82 100.73,17.82 IC6.9 | v94.36,21.37 v95.17,21.37 | v93.95,44.92 93.42,45.45 93.37,45.45 93.34,45.48 83.66,45.48 82.85,46.29 v80.28,46.29 | v79.27,41.36 v80.28,41.36
DQ5  (via drill 0.61)
  Top 0.203: v92.73,22.19 92.32,22.59 92.32,27.77 v92.73,28.18
  Bottom 0.203: v92.73,22.19 95.09,22.19 95.3,22.39 100.68,22.39 IC6.7 | v92.73,28.18 90.27,28.18 89.53,28.92 85.85,28.92 85.82,28.89 85.16,28.89 83.87,30.19 82.19,30.19 IC9.4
